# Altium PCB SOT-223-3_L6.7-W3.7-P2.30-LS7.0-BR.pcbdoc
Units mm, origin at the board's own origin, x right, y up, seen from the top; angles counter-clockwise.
Board outline 21.31 x 19.55 mm, 2 copper layers (Top Layer, Bottom Layer), stack 0 mm thick; 1 components, 0 nets, 4 pads, 0 vias.
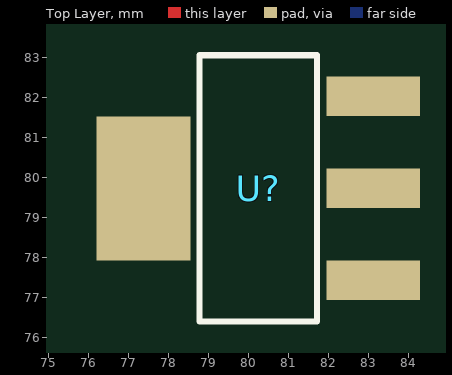
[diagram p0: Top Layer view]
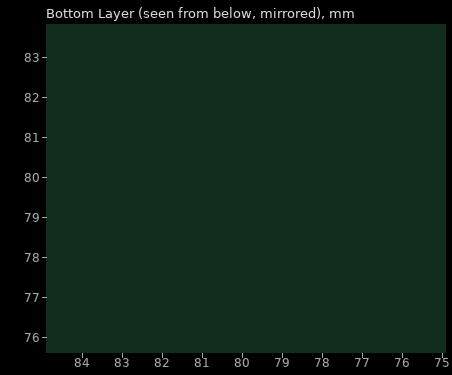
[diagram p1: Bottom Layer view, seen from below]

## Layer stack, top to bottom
Top Layer: signal copper (thickness not stored)
Bottom Layer: signal copper (thickness not stored)

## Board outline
91.158,69.85 69.85,69.85 69.85,89.401 91.158,89.401

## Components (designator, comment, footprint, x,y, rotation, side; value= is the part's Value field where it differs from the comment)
U? "" SOT-223-3_L6.7-W3.7-P2.30-LS7.0-BR 80.24,79.725 r0 top

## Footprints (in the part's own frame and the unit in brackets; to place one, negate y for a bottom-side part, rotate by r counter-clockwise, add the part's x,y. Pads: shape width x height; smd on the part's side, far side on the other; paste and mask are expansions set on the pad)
SOT-223-3_L6.7-W3.7-P2.30-LS7.0-BR [mm]
  rect 2.34x0.98 smd: 1(2.87,-2.3) 2(2.87,0) 3(2.87,2.3)
  rect 2.34x3.6 smd: 4(-2.87,0)
  silkscreen extent -1.47,-3.33 1.47,3.33

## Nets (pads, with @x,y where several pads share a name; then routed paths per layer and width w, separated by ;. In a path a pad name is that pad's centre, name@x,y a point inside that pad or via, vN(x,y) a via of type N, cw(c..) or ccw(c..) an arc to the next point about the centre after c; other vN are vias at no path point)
pads on no net: U?.1 U?.2 U?.3 U?.4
